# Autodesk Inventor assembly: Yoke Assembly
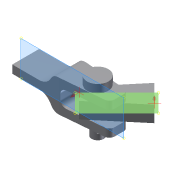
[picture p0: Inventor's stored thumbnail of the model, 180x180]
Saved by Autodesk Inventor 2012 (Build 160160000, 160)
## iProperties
Created: 2012-02
Part Number: Yoke Assembly
Document SubType Name: Assembly
Designer: cadcim
Author: cadcim
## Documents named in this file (4)
- C:\ANSYS_WB\c10\Tut03\Assembly\Yoke Assembly.iam
- C:\ANSYS_WB\c10\Tut03\Assembly\Yoke.ipt
- C:\ANSYS_WB\c10\Tut03\Assembly\Stem.ipt
- C:\ANSYS_WB\c10\Tut03\Assembly\pIN.ipt
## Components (3 placed, 3 different names)
1. Yoke:1 — Mate:6, Mate:8, Mate:9, Angle:1
2. Stem:1 — Mate:7, Mate:9, Angle:1
3. pIN:1 — Mate:6, Mate:7, Mate:8
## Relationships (5: Mate 4, Angle 1)
- Mate:6: Yoke:1 ↔ pIN:1
- Mate:7: Stem:1 ↔ pIN:1
- Mate:8: Yoke:1 ↔ pIN:1
- Mate:9: Yoke:1 ↔ Stem:1
- Angle:1: Yoke:1 ↔ Stem:1
